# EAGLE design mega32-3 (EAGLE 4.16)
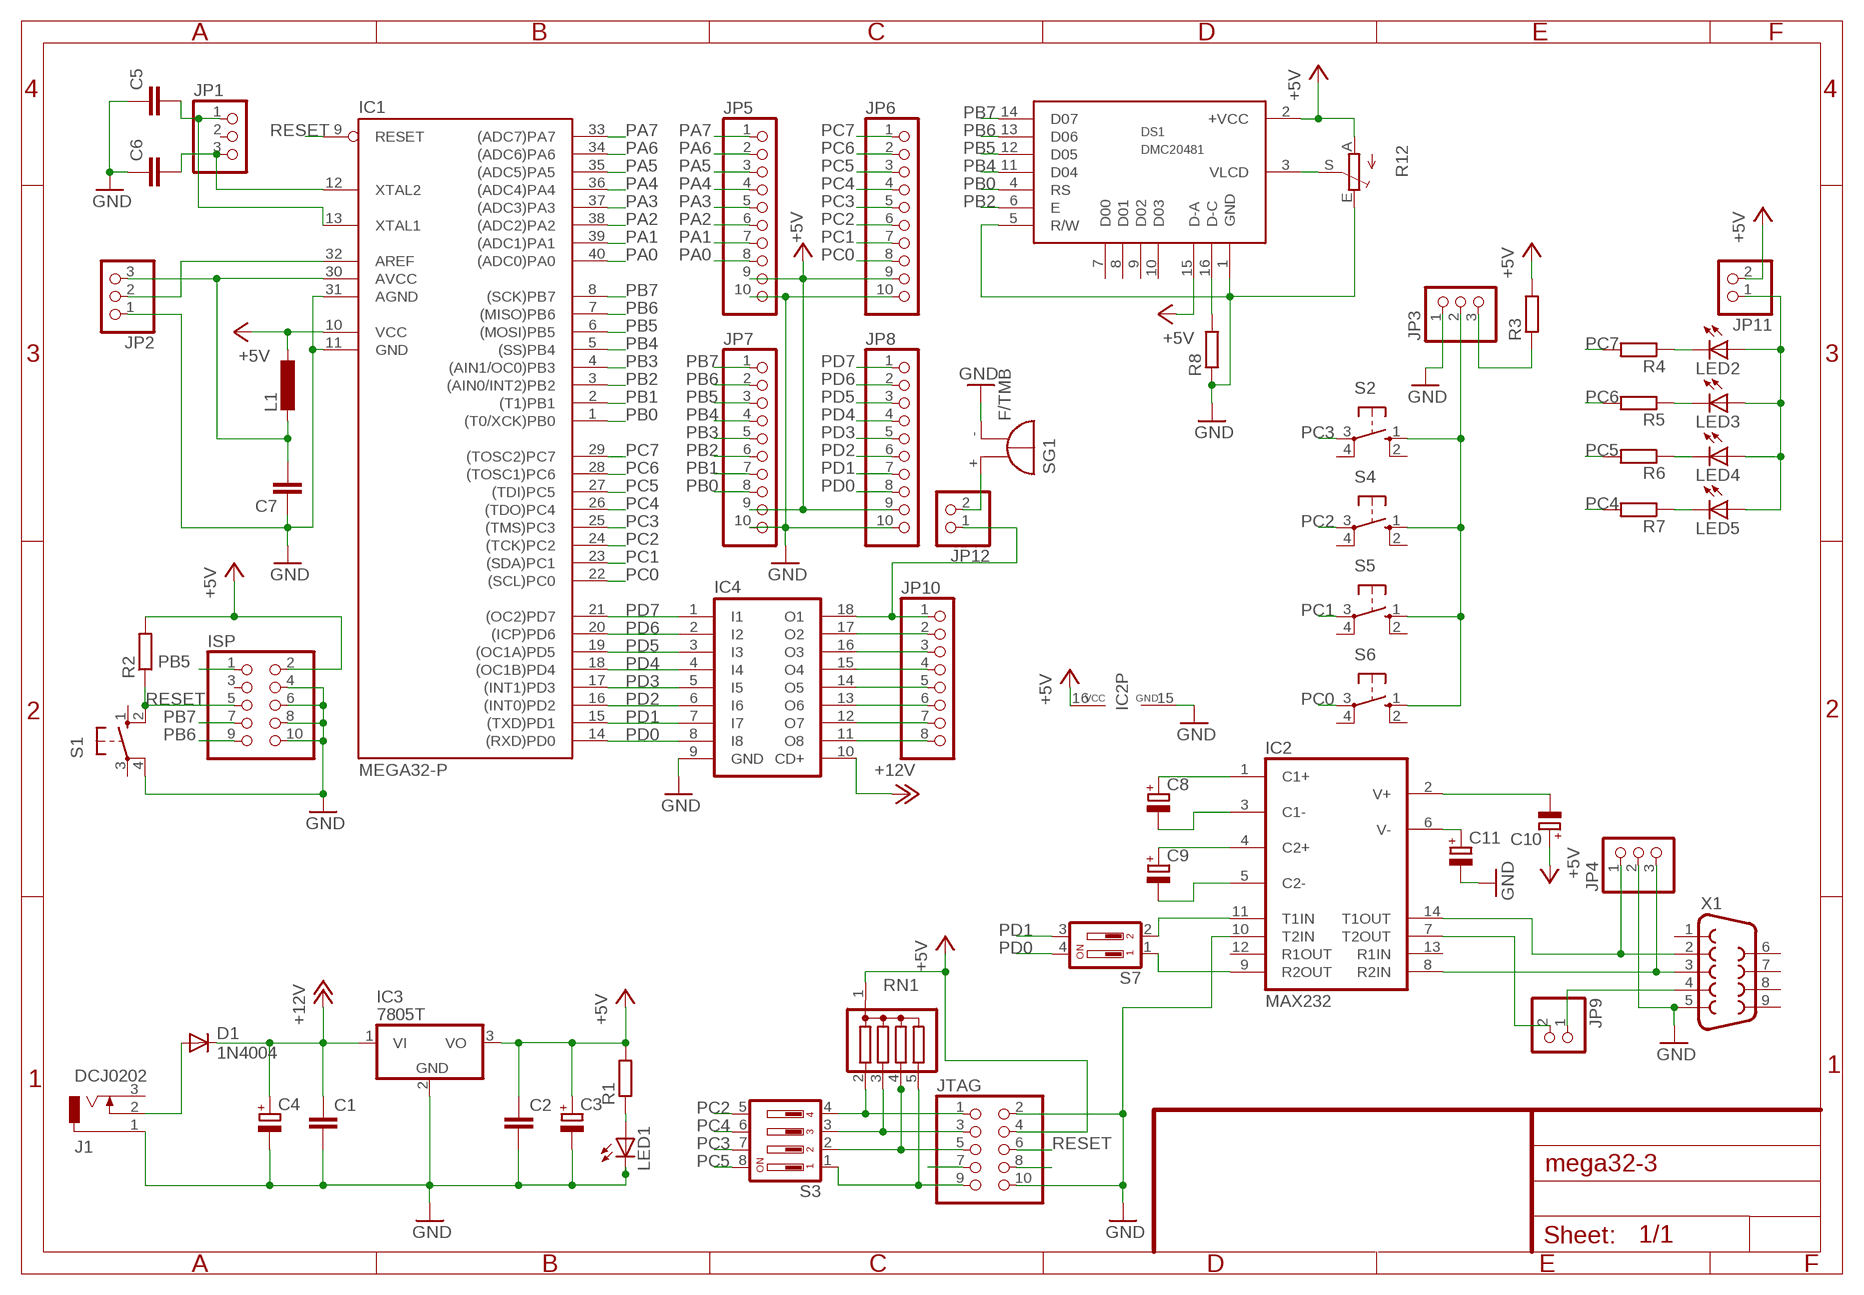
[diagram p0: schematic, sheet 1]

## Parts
C1  C-EU050-024X044  [C050-024X044]
C2  C-EU050-024X044  [C050-024X044]
C3  CPOL-EUE2.5-6  [E2,5-6]
C4  CPOL-EUE2.5-7  [E2,5-7]
C5  C-EU050-024X044  [C050-024X044]
C6  C-EU050-024X044  [C050-024X044]
C7  C-EU050-024X044  [C050-024X044]
C8  CPOL-EUE2.5-6  [E2,5-6]
C9  CPOL-EUE2.5-6  [E2,5-6]
C10  CPOL-EUE2.5-6  [E2,5-6]
C11  CPOL-EUE2.5-6  [E2,5-6]
D1  1N4004  [DO41-10]
DS1  DMC20481  [DM20481]
IC1  MEGA32-P  [DIL40]
IC2  MAX232  [DIL16]
IC3  7805T  [TO220H]
IC4  ULN2803A  [DIL18]
ISP  PINHD-2X5  [2X05]
J1  DCJ0202  [DCJ0202]
JP1  PINHD-1X3  [1X03]
JP2  PINHD-1X3  [1X03]
JP3  PINHD-1X3  [1X03]
JP4  PINHD-1X3  [1X03]
JP5  PINHD-1X10  [1X10]
JP6  PINHD-1X10  [1X10]
JP7  PINHD-1X10  [1X10]
JP8  PINHD-1X10  [1X10]
JP9  PINHD-1X2  [1X02]
JP10  PINHD-1X8  [1X08]
JP11  PINHD-1X2  [1X02]
JP12  PINHD-1X2  [1X02]
JTAG  PINHD-2X5  [2X05]
L1  L-EU0207/10  [0207/10]
LED1  LED5MM  [LED5MM]
LED2  LED5MM  [LED5MM]
LED3  LED5MM  [LED5MM]
LED4  LED5MM  [LED5MM]
LED5  LED5MM  [LED5MM]
R1  R-EU_0207/10  [0207/10]
R2  R-EU_0207/10  [0207/10]
R3  R-EU_0207/10  [0207/10]
R4  R-EU_0207/10  [0207/10]
R5  R-EU_0207/10  [0207/10]
R6  R-EU_0207/10  [0207/10]
R7  R-EU_0207/10  [0207/10]
R8  R-EU_0207/10  [0207/10]
R12  TRIM_EU-B64Y  [B64Y]
RN1  G04R  [SIL5]
S1  10-XX  [B3F-10XX]
S2  10-XX  [B3F-10XX]
S3  DIP04YL  [DIP04YL]
S4  10-XX  [B3F-10XX]
S5  10-XX  [B3F-10XX]
S6  10-XX  [B3F-10XX]
S7  DIP02YL  [DIP02YL]
SG1  F/TMB  [F/TMB]
X1  F09H  [F09H]

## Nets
+5V: C2.1 C3.+ C10.+ DS1.2(+VCC) DS1.15(D-A) IC1.10(VCC) IC2.16(VCC) IC3.3(VO) ISP.2 JP5.9 JP6.9 JP7.9 JP8.9 JP11.2 JTAG.4 L1.1 R1.2 R2.2 R3.2 R12.A RN1.1
+12V: C1.1 C4.+ D1.C IC3.1(VI) IC4.10(CD+)
GND: C1.2 C2.2 C3.- C4.- C5.1 C6.1 C7.1 C11.- DS1.1(GND) DS1.5(R/W) IC1.11(GND) IC1.31(AGND) IC2.10(T2IN) IC2.15(GND) IC3.2(GND) IC4.9(GND) ISP.4 ISP.6 ISP.8 ISP.10 J1.1 JP2.1 JP3.1 JP4.2 JP5.10 JP6.10 JP7.10 JP8.10 JTAG.2 JTAG.10 LED1.K(C) R8.1 R12.E S1.4(P1) SG1.- X1.5
N$1: C7.2 IC1.30(AVCC) JP2.3 L1.2
N$2: IC1.32(AREF) JP2.2
N$4: JP3.2 S2.1(S) S4.1(S) S5.1(S) S6.1(S)
N$5: C8.+ IC2.1(C1+)
N$6: C8.- IC2.3(C1-)
N$7: C9.+ IC2.4(C2+)
N$8: C9.- IC2.5(C2-)
N$9: IC2.14(T1OUT) JP4.1 X1.2
N$10: IC2.8(R2IN) JP4.3 X1.3
N$11: C10.- IC2.2(V+)
N$12: C11.+ IC2.6(V-)
N$13: IC2.11(T1IN) S7.2
N$14: IC2.9(R2OUT) S7.1
N$15: JP3.3 R3.1
N$16: JP9.1 X1.4
N$17: JTAG.7
N$18: IC4.18(O1) JP10.1 JP12.1
N$19: DS1.16(D-C) R8.2
N$20: JTAG.8
N$21: JP12.2 SG1.+
N$23: LED5.K(C) R7.1
N$24: LED4.K(C) R6.1
N$25: LED3.K(C) R5.1
N$26: LED2.K(C) R4.1
N$27: IC2.7(T2OUT) JP9.2
N$29: DS1.3(VLCD) R12.S
N$30: C5.2 IC1.13(XTAL1) JP1.1
N$31: C6.2 IC1.12(XTAL2) JP1.3
N$32: IC4.17(O2) JP10.2
N$33: IC4.16(O3) JP10.3
N$34: IC4.15(O4) JP10.4
N$35: IC4.14(O5) JP10.5
N$36: IC4.13(O6) JP10.6
N$37: IC4.12(O7) JP10.7
N$38: IC4.11(O8) JP10.8
N$39: JP11.1 LED2.A LED3.A LED4.A LED5.A
N$71: D1.A J1.2
N$73: LED1.A R1.1
N$111: JTAG.3 RN1.3 S3.3
N$222: JTAG.1 RN1.2 S3.4
N$333: JTAG.5 RN1.4 S3.2
N$444: JTAG.9 RN1.5 S3.1
PA0: IC1.40((ADC0)PA0) JP5.8
PA1: IC1.39((ADC1)PA1) JP5.7
PA2: IC1.38((ADC2)PA2) JP5.6
PA3: IC1.37((ADC3)PA3) JP5.5
PA4: IC1.36((ADC4)PA4) JP5.4
PA5: IC1.35((ADC5)PA5) JP5.3
PA6: IC1.34((ADC6)PA6) JP5.2
PA7: IC1.33((ADC7)PA7) JP5.1
PB0: DS1.4(RS) IC1.1((T0/XCK)PB0) JP7.8
PB1: IC1.2((T1)PB1) JP7.7
PB2: DS1.6(E) IC1.3((AIN0/INT2)PB2) JP7.6
PB3: IC1.4((AIN1/OC0)PB3) JP7.5
PB4: DS1.11(D04) IC1.5((SS)PB4) JP7.4
PB5: DS1.12(D05) IC1.6((MOSI)PB5) ISP.1 JP7.3
PB6: DS1.13(D06) IC1.7((MISO)PB6) ISP.9 JP7.2
PB7: DS1.14(D07) IC1.8((SCK)PB7) ISP.7 JP7.1
PC0: IC1.22((SCL)PC0) JP6.8 S6.3(P)
PC1: IC1.23((SDA)PC1) JP6.7 S5.3(P)
PC2: IC1.24((TCK)PC2) JP6.6 S3.5 S4.3(P)
PC3: IC1.25((TMS)PC3) JP6.5 S2.3(P) S3.7
PC4: IC1.26((TDO)PC4) JP6.4 R7.2 S3.6
PC5: IC1.27((TDI)PC5) JP6.3 R6.2 S3.8
PC6: IC1.28((TOSC1)PC6) JP6.2 R5.2
PC7: IC1.29((TOSC2)PC7) JP6.1 R4.2
PD0: IC1.14((RXD)PD0) IC4.8(I8) JP8.8 S7.4
PD1: IC1.15((TXD)PD1) IC4.7(I7) JP8.7 S7.3
PD2: IC1.16((INT0)PD2) IC4.6(I6) JP8.6
PD3: IC1.17((INT1)PD3) IC4.5(I5) JP8.5
PD4: IC1.18((OC1B)PD4) IC4.4(I4) JP8.4
PD5: IC1.19((OC1A)PD5) IC4.3(I3) JP8.3
PD6: IC1.20((ICP)PD6) IC4.2(I2) JP8.2
PD7: IC1.21((OC2)PD7) IC4.1(I1) JP8.1
RESET: IC1.9(RESET) ISP.5 JTAG.6 R2.1 S1.2(S1)
Unconnected: DS1.7(D00) DS1.8(D01) DS1.9(D02) DS1.10(D03) IC2.12(R1OUT) IC2.13(R1IN) ISP.3 J1.3 JP1.2 S1.1(S) S1.3(P) S2.2(S1) S2.4(P1) S4.2(S1) S4.4(P1) S5.2(S1) S5.4(P1) S6.2(S1) S6.4(P1) X1.1 X1.6 X1.7 X1.8 X1.9

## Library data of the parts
C1 C2 C5-C7 = rcl:C-EU: CAPACITOR, European symbol
C3 C4 C8-C11 = rcl:CPOL-EU: POLARIZED CAPACITOR, European symbol
D1 = diode:1N4004: DIODE
DS1 = abi-lcd:DMC20481
IC1 = atmel:MEGA32-P: MICROCONTROLLER 32 Kbytes FLASH 2 Kbytes SRAM 1 Kbytes EEPROM USART 8-channel 10 bit ADC Source: www.atmel.com .. doc2503.pdf
IC2 = maxim:MAX232: RS232 TRANSEIVER
IC3 = linear:78*: Positive VOLTAGE REGULATOR Source: http://cache.national.com/ds/LM/LM78L05.pdf http://www.fairchildsemi.com/ds/LM/LM7805.pdf
IC4 = uln-udn:ULN2803A: DRIVER ARRAY
ISP JTAG = pinhead:PINHD-2X5: PIN HEADER
J1 = con-jack:DCJ0202: DC POWER JACK Source: DCJ0202.pdf
JP1-JP4 = pinhead:PINHD-1X3: PIN HEADER
JP5-JP8 = pinhead:PINHD-1X10: PIN HEADER
JP9 JP11 JP12 = pinhead:PINHD-1X2: PIN HEADER
JP10 = pinhead:PINHD-1X8: PIN HEADER
L1 = rcl:L-EU: INDUCTOR, European symbol
LED1-LED5 = led:LED: LED
R1-R8 = rcl:R-EU_: RESISTOR, European symbol
R12 = pot:TRIM_EU-: POTENTIOMETER
RN1 = resistor-sil:G04R: SIL RESISTOR
S1 S2 S4-S6 = switch-omron:10-XX: OMRON SWITCH
S3 = switch-dil:DIP04YL: DIL/CODE SWITCH
S7 = switch-dil:DIP02YL: DIL/CODE SWITCH
SG1 = buzzer:F/TMB: BUZZER
X1 = con-subd:F09: SUB-D

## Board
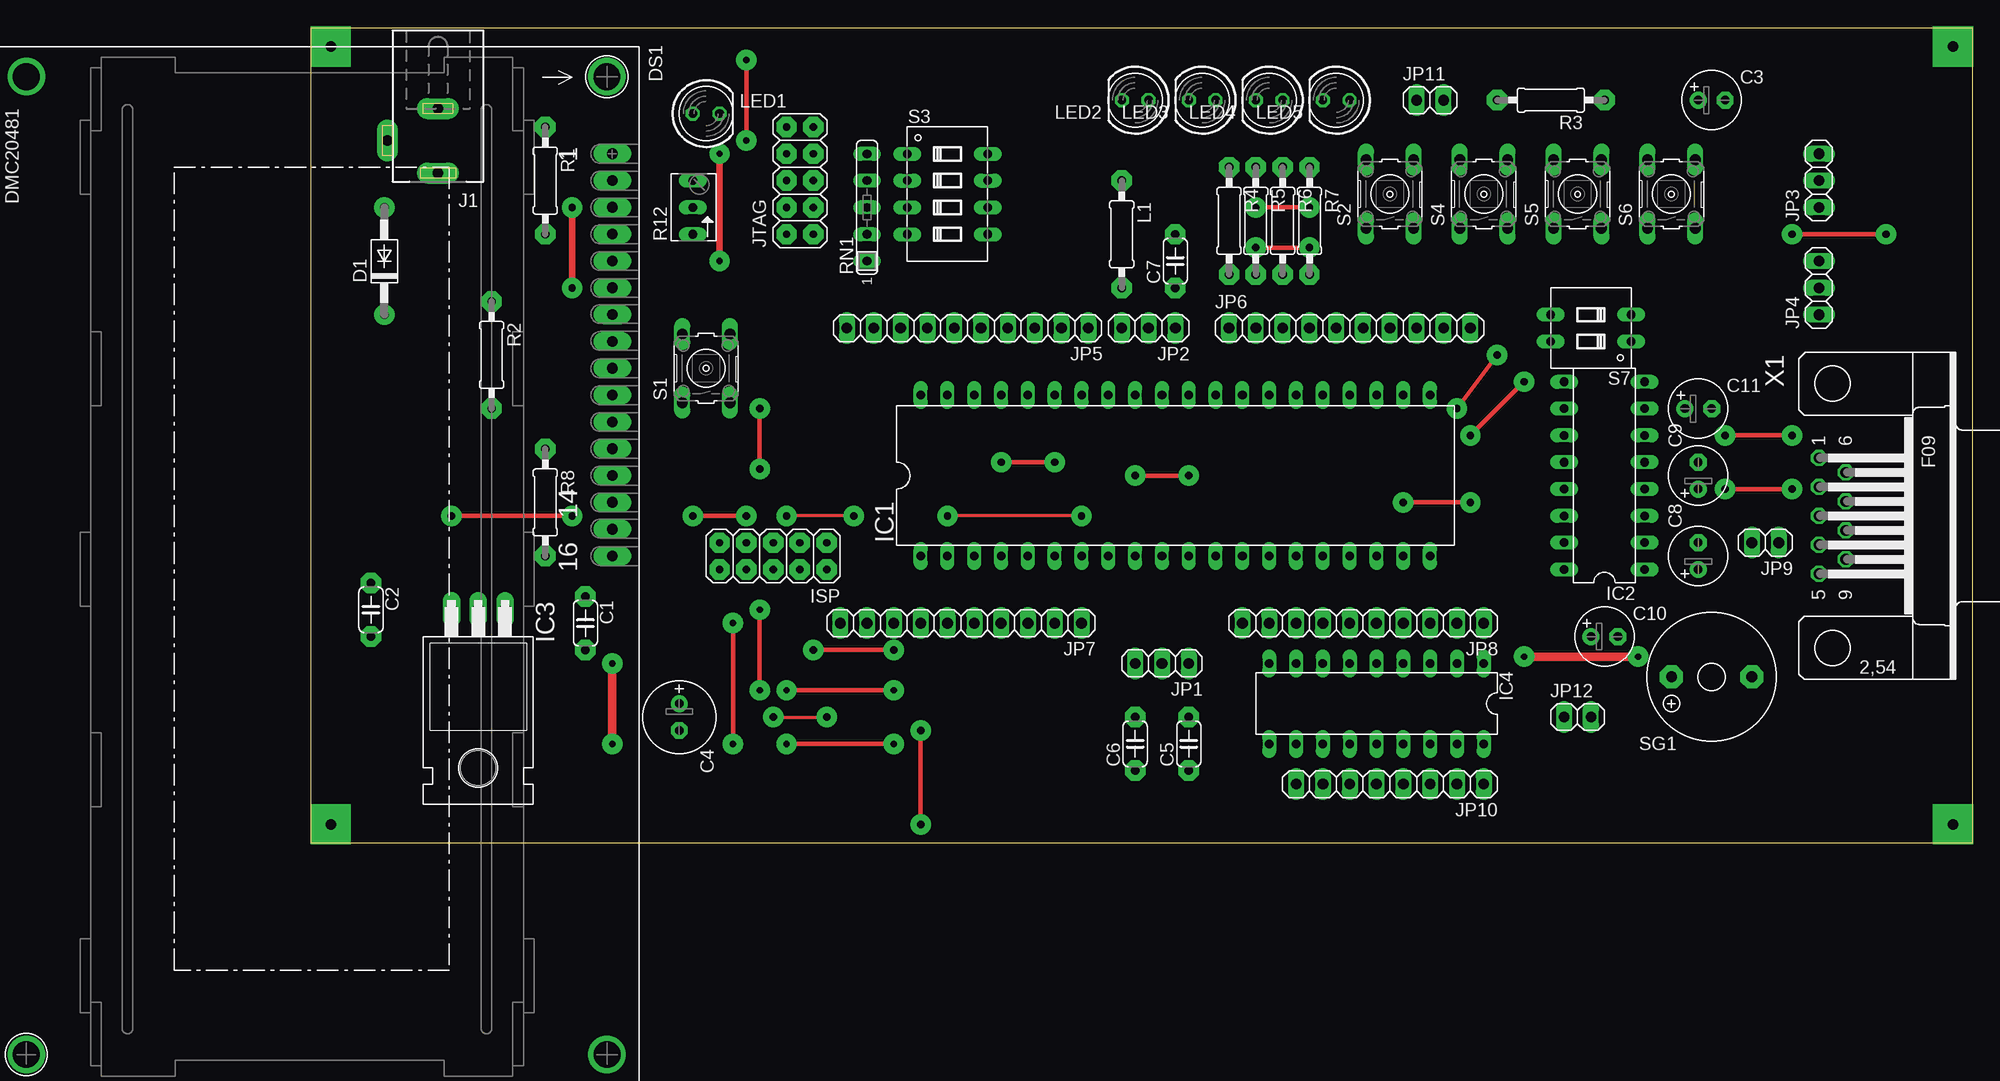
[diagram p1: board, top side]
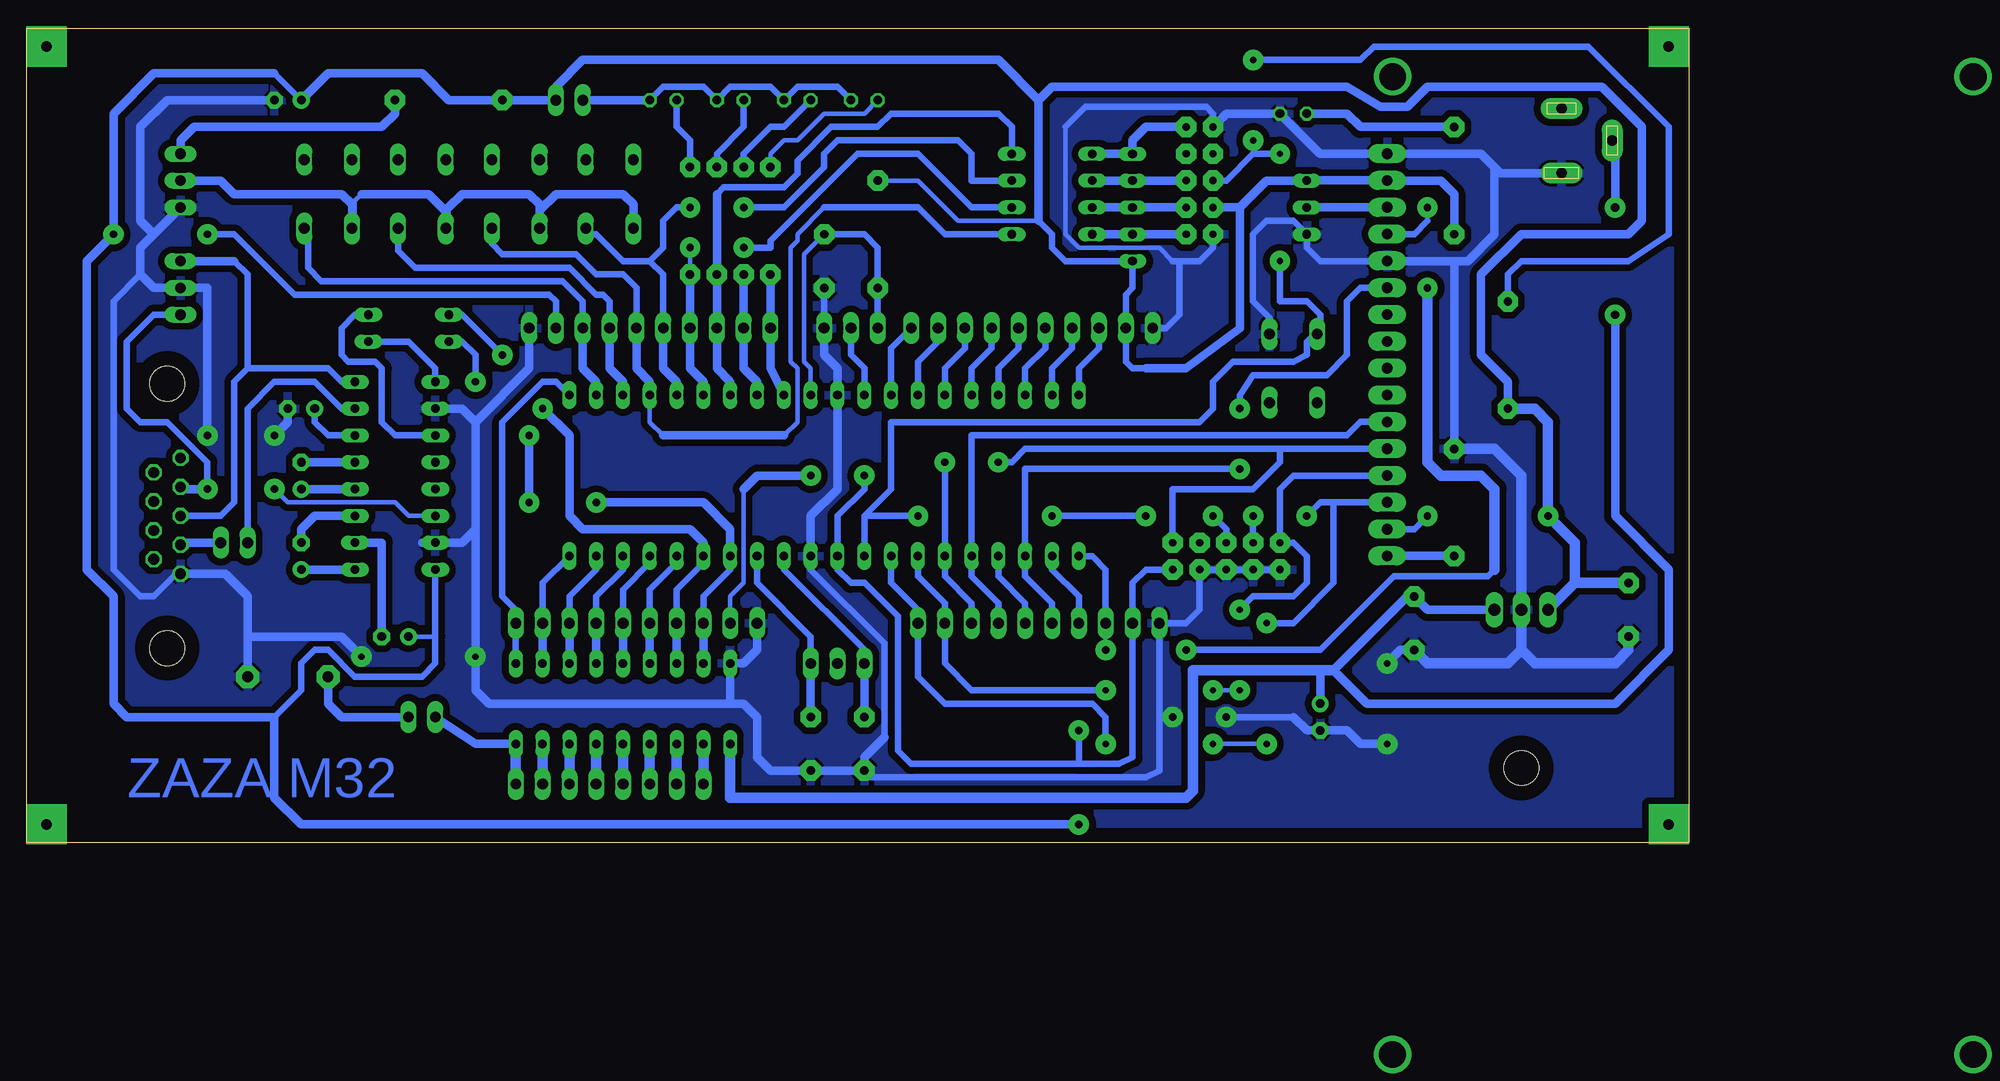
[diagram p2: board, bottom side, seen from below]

Size 157.46 x 77.14 mm. Coordinates in mm from the lower left corner, seen from the top.
Outline: 0,0 157.46,0 157.46,77.14 0,77.14 0,0
Copper layers (1*16): Top 0.035mm / dielectric 1.5mm / Bottom 0.035mm
Design rules "default": minimum track width 10mil, minimum drill 24mil, track to track 25mil, track to pad 25mil, pad to pad 25mil, via to via 25mil, smd to smd 25mil, copper to edge 55mil, drill to drill 10mil, minimum pad ring 10mil, minimum via ring 8mil, stop-mask expansion 4mil, vias tented up to drill 0mil, thermal gap 10mil

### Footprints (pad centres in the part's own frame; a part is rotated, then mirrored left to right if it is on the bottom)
C050-024X044 = drill 0.8 pad 1.93 octagon: 1 -2.54,0; 2 2.54,0
E2,5-6 = drill 0.813 pad 1.6 round: + -1.27,0 | drill 0.813 pad 1.6 octagon: - 1.27,0
E2,5-7 = drill 0.813 pad 1.6 round: + -1.27,0 | drill 0.813 pad 1.6 octagon: - 1.27,0
DO41-10 = drill 0.8 pad 1.93 round: A 5.08,0; C -5.08,0
DM20481 = drill 1.016 pad 1.778 long: 1 -39.383,29.21; 2 -36.843,29.21; 3 -34.303,29.21; 4 -31.763,29.21; 5 -29.223,29.21; 6 -26.683,29.21; 7 -24.143,29.21; 8 -21.603,29.21; 9 -19.063,29.21; 10 -16.523,29.21; 11 -13.983,29.21; 12 -11.443,29.21; 13 -8.903,29.21; 14 -6.363,29.21; 15 -3.823,29.21; 16 -1.283,29.21 | drill 2.54 pad 0.254 round: P$1 -46.672,-26.289; P$2 45.936,-26.289; P$3 45.936,28.715; P$4 -46.672,28.702
DIL40 = drill 0.813 long: 1 -24.13,-7.62; 2 -21.59,-7.62; 3 -19.05,-7.62; 4 -16.51,-7.62; 5 -13.97,-7.62; 6 -11.43,-7.62; 7 -8.89,-7.62; 8 -6.35,-7.62; 9 -3.81,-7.62; 10 -1.27,-7.62; 11 1.27,-7.62; 12 3.81,-7.62; 13 6.35,-7.62; 14 8.89,-7.62; 15 11.43,-7.62; 16 13.97,-7.62; 17 16.51,-7.62; 18 19.05,-7.62; 19 21.59,-7.62; 20 24.13,-7.62; 21 24.13,7.62; 22 21.59,7.62; 23 19.05,7.62; 24 16.51,7.62; 25 13.97,7.62; 26 11.43,7.62; 27 8.89,7.62; 28 6.35,7.62; 29 3.81,7.62; 30 1.27,7.62; 31 -1.27,7.62; 32 -3.81,7.62; 33 -6.35,7.62; 34 -8.89,7.62; 35 -11.43,7.62; 36 -13.97,7.62; 37 -16.51,7.62; 38 -19.05,7.62; 39 -21.59,7.62; 40 -24.13,7.62
DIL16 = drill 0.813 long: 1 -8.89,-3.81; 2 -6.35,-3.81; 3 -3.81,-3.81; 4 -1.27,-3.81; 5 1.27,-3.81; 6 3.81,-3.81; 7 6.35,-3.81; 8 8.89,-3.81; 9 8.89,3.81; 10 6.35,3.81; 11 3.81,3.81; 12 1.27,3.81; 13 -1.27,3.81; 14 -3.81,3.81; 15 -6.35,3.81; 16 -8.89,3.81
TO220H = drill 1.118 long: 1 -2.54,-10.16; 2 0,-10.16; 3 2.54,-10.16 | hole 3.302: 0,4.826
DIL18 = drill 0.813 long: 1 -10.16,-3.81; 2 -7.62,-3.81; 3 -5.08,-3.81; 4 -2.54,-3.81; 5 0,-3.81; 6 2.54,-3.81; 7 5.08,-3.81; 8 7.62,-3.81; 9 10.16,-3.81; 10 10.16,3.81; 11 7.62,3.81; 12 5.08,3.81; 13 2.54,3.81; 14 0,3.81; 15 -2.54,3.81; 16 -5.08,3.81; 17 -7.62,3.81; 18 -10.16,3.81
2X05 = drill 0.7 pad 1.93 octagon: 1 -5.08,-1.27; 2 -5.08,1.27; 3 -2.54,-1.27; 4 -2.54,1.27; 5 0,-1.27; 6 0,1.27; 7 2.54,-1.27; 8 2.54,1.27; 9 5.08,-1.27; 10 5.08,1.27
DCJ0202 = drill 1 pad 2 long: 1 0,3.1; 2 4.8,0; 3 0,-3
1X03 = drill 1.016 long: 1 -2.54,0; 2 0,0; 3 2.54,0
1X10 = drill 1.016 long: 1 -11.43,0; 2 -8.89,0; 3 -6.35,0; 4 -3.81,0; 5 -1.27,0; 6 1.27,0; 7 3.81,0; 8 6.35,0; 9 8.89,0; 10 11.43,0
1X02 = drill 1.016 long: 1 -1.27,0; 2 1.27,0
1X08 = drill 1.016 long: 1 -8.89,0; 2 -6.35,0; 3 -3.81,0; 4 -1.27,0; 5 1.27,0; 6 3.81,0; 7 6.35,0; 8 8.89,0
0207/10 = drill 0.8 pad 1.93 octagon: 1 -5.08,0; 2 5.08,0
LED5MM = drill 0.813 octagon: A -1.27,0; K 1.27,0
B64Y = drill 0.813 long: A 2.54,0; E -2.54,0; S 0,0
SIL5 = drill 0.813 long: 1 -5.08,0; 2 -2.54,0; 3 0,0; 4 2.54,0; 5 5.08,0
B3F-10XX = drill 1.016 long: 1 -3.251,2.261; 2 3.251,2.261; 3 -3.251,-2.261; 4 3.251,-2.261
DIP04YL = drill 0.813 long: 1 -3.81,-3.81; 2 -1.27,-3.81; 3 1.27,-3.81; 4 3.81,-3.81; 5 3.81,3.81; 6 1.27,3.81; 7 -1.27,3.81; 8 -3.81,3.81
DIP02YL = drill 0.813 long: 1 -1.27,-3.81; 2 1.27,-3.81; 3 1.27,3.81; 4 -1.27,3.81
F/TMB = drill 1.016 pad 2.159 octagon: + 3.81,0; - -3.81,0
F09H = drill 1.016 octagon: 1 -5.486,-1.27; 2 -2.743,-1.27; 3 0,-1.27; 4 2.743,-1.27; 5 5.486,-1.27; 6 -4.115,1.27; 7 -1.372,1.27; 8 1.372,1.27; 9 4.115,1.27 | hole 3.302: -12.522,0; 12.522,0

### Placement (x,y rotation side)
C1  26.03,20.79 270 top
C2  5.71,22.06 270 top
C3  132.71,70.32 0 top
C4  34.92,11.9 270 top
C5  83.18,9.36 90 top
C6  78.1,9.36 90 top
C7  81.91,55.08 90 top
C8  131.44,27.14 90 top
C9  131.44,34.76 90 top
C10  122.55,19.52 0 top
C11  131.44,41.11 0 top
D1  6.98,55.08 90 top
DS1  -0.64,25.87 270 top
IC1  81.91,34.76 0 top
IC2  122.55,34.76 90 top
IC3  15.87,11.9 180 top
IC4  100.96,13.17 180 top
ISP  43.81,27.14 180 top
J1  12.06,66.51 180 top
JP1  80.64,16.98 180 top
JP2  79.37,48.73 180 top
JP3  142.87,62.7 90 top
JP4  142.87,52.54 90 top
JP5  62.23,48.73 180 top
JP6  98.42,48.73 0 top
JP7  61.59,20.79 180 top
JP8  99.69,20.79 180 top
JP9  137.79,28.41 180 top
JP10  102.23,5.55 180 top
JP11  106.04,70.32 0 top
JP12  120.01,11.9 0 top
JTAG  46.35,62.7 90 top
L1  76.83,57.62 270 top
LED1  37.46,69.05 0 top
LED2  78.1,70.32 180 top
LED3  84.45,70.32 180 top
LED4  90.8,70.32 180 top
LED5  97.15,70.32 180 top
R1  22.22,62.7 270 top
R2  17.14,46.19 270 top
R3  117.47,70.32 180 top
R4  86.99,58.89 270 top
R5  89.53,58.89 270 top
R6  92.07,58.89 270 top
R7  94.61,58.89 270 top
R8  22.22,32.22 270 top
R12  36.19,60.16 90 top
RN1  52.7,60.16 90 top
S1  37.46,44.92 90 top
S2  102.23,61.43 90 top
S3  60.32,61.43 270 top
S4  111.12,61.43 90 top
S5  120.01,61.43 90 top
S6  128.9,61.43 90 top
S7  121.28,48.73 90 top
SG1  132.71,15.71 180 top
X1  144.14,30.95 270 top

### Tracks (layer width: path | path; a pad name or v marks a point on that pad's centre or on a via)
+5V  (via drill 0.7 pad 1.93)
  Top 0.406: v149.22,57.62 v140.33,57.62 | v78.1,34.76 v83.18,34.76 | v57.78,1.74 v57.78,10.63 | v13.33,30.95 v24.76,30.95
  Bottom 0.406: DS1.2 | R12.A 36.18,62.71 | 61.59,58.89 69.21,58.89 73.02,62.7 L1.1 | JP8.9 90.8,23.33 89.53,24.6 89.53,33.49 | 118.74,19.52 C10.+
  Bottom 0.61: 61.59,58.89 60.32,57.62 60.32,56.35 59.05,55.08 RN1.1 52.7,52.54 53.34,51.91 JP5.9 53.34,45.56 52.7,44.92 51.43,44.92 | JP6.9 107.31,51.27 107.94,51.91 132.07,51.91 137.79,57.62 v140.33,57.62 | C3.+ 133.98,72.86 | IC2.16 118.74,19.52 118.74,16.98 120.01,15.71 126.36,15.71 128.9,18.25 130.17,18.25 131.44,16.98 131.44,14.44 133.98,11.9 | v78.1,34.76 78.1,33.49 80.64,30.95 IC1.10 80.64,25.87 79.37,24.6 78.1,24.6 74.92,21.43 74.92,8.73 73.66,7.46 57.78,7.46 | 57.78,7.46 53.97,7.46 52.7,8.09 JP7.9 52.7,24.6 51.43,25.87 ISP.2 | DS1.15 26.02,29.69 v24.76,30.95 | v57.78,10.63 57.78,7.46
  Bottom 0.813: R1.2 22.22,61.43 23.49,62.7 DS1.2 | 36.18,62.71 DS1.2 | R12.A 40,62.7 42.54,60.16 | 42.54,60.16 JTAG.4 | 51.43,44.92 47.62,44.92 42.54,48.73 42.54,60.16 | C3.+ 128.9,72.86 120.01,72.86 117.47,70.32 R3.2 JP11.2 107.31,71.59 104.77,74.13 65.4,74.13 61.59,70.32 | 133.98,72.86 145.41,72.86 149.22,69.05 v149.22,57.62 151.76,55.08 151.76,25.87 149.22,23.33 149.22,13.17 147.95,11.9 133.98,11.9 133.98,4.28 131.44,1.74 v57.78,1.74 | 89.53,33.49 88.26,34.76 v83.18,34.76 | 61.59,70.32 61.59,58.89 | R2.2 17.14,43.65 19.68,46.19 19.68,53.81 15.87,57.62 5.71,57.62 4.44,58.89 4.44,67.78 8.25,71.59 24.76,71.59 26.66,69.69 29.2,69.69 32.38,71.59 60.32,71.59 61.59,70.32
  Bottom 1.016: 10.79,24.6 IC3.3 | C2.1 10.79,24.6 | 10.79,24.6 10.79,28.41 v13.33,30.95 13.33,39.84 14.6,41.11 R2.2
+12V
  Bottom 0.813: D1.C 6.98,30.95 1.9,25.87 1.9,18.25 6.98,13.17 30.47,13.17 33.65,16.34 26.66,23.33 C1.1 24.76,22.06 IC3.1 | 34.92,16.34 C4.+
  Bottom 1.016: IC4.10 90.8,4.28 47.62,4.28 46.98,4.91 46.98,16.34 34.92,16.34 33.65,16.34
GND  (via drill 0.6 pad 1.93, 0.7 pad 1.93)
  Top 0.305: v43.81,11.9 v48.89,11.9
  Top 0.406: v140.33,38.57 v133.98,38.57
  Top 0.813: v28.57,16.98 v28.57,9.36 | v114.93,17.61 v125.72,17.61
  Bottom 0.305: v48.89,11.9 50.16,11.9
  Bottom 0.406: 34.93,65.25 DS1.1 | 48.89,55.08 50.16,56.35 57.78,56.35 59.05,57.62 59.05,67.78 | DS1.5 | 138.65,25.46 X1.5
  Bottom 0.61: JP2.1 C7.1 | JTAG.2 45.08,56.35 46.35,55.08 48.26,55.08 | 48.89,55.08 48.26,55.08 | DS1.5 34.92,55.08 36.19,56.35 R12.E 37.46,58.89 40,58.89 41.27,57.62 41.27,51.27 39.72,49.72 S1.4 | JTAG.10 45.08,69.05 45.72,69.69 57.15,69.69 59.05,67.78 | 37.46,11.9 v43.81,11.9 | ISP.10 ISP.8 ISP.6 ISP.4 46.35,22.06 47.62,20.79 JP7.10 50.16,11.9 50.16,6.82 51.43,6.18 77.46,6.18 C6.1 | IC1.11 83.18,25.87 76.19,18.89 76.19,10 | 143.28,25.46 145.41,23.33 146.68,23.33 149.22,25.87 149.22,51.27 146.68,53.81 | JP5.10 49.53,48.73 48.26,50 48.26,55.08
  Bottom 0.813: JP2.1 81.91,46.19 80.64,44.92 IC1.31 80.64,33.49 83.18,30.95 IC1.11 | 145.41,57.62 146.68,56.35 146.68,53.81 145.41,52.54 JP4.2 140.33,52.54 v140.33,38.57 | 114.93,29.68 116.2,28.41 IC2.15 120.01,28.41 | 114.93,29.68 114.93,39.84 | 114.93,39.84 116.2,41.11 IC2.10 | JP8.10 88.26,18.25 89.53,16.98 IC4.9 90.8,13.17 | 90.8,13.17 113.66,13.17 114.93,14.44 v114.93,17.61 114.93,29.68 | JP6.10 109.85,44.92 114.93,39.84 | JTAG.10 43.81,69.05 LED1.K 34.93,65.25 19.69,65.25 18.41,63.97 | 18.41,63.97 18.41,57.62 20.95,55.08 22.22,55.08 | 22.22,55.08 DS1.5 | J1.1 17.85,63.41 18.41,63.97 | R8.1 22.22,55.08 | 90.8,13.17 89.53,13.17 88.26,11.9 88.26,8.09 86.99,6.82 C5.1 C6.1 78.1,8.09 76.19,10 | 145.41,57.62 JP3.1 | C3.- 144.14,70.32 146.68,67.78 146.68,58.89 145.41,57.62 | 136.52,19.52 SG1.- | 136.52,19.52 136.52,23.33 138.65,25.46 143.28,25.46 | 136.52,19.52 127.63,19.52 v125.72,17.61 | 37.46,11.9 36.19,10.63 C4.- 32.38,10.63 31.11,9.36 v28.57,9.36 | C1.2 27.3,18.25 v28.57,16.98 | C11.- 132.71,39.84 v133.98,38.57
  Bottom 1.016: C2.2 5.71,18.25 6.98,16.98 14.6,16.98 15.87,18.25 | 15.87,18.25 IC3.2 15.87,34.76 18.41,37.3 R8.1 | 15.87,18.25 17.14,16.98 24.76,16.98 C1.2
  pour Bottom: -0.64,79.21 -0.64,-2.07 0.63,-3.34 156.84,-3.34 160.65,0.47 160.65,76.67 156.84,80.48 0.63,80.48
N$1
  Bottom 0.406: IC1.30 83.18,44.92 83.81,45.56 83.81,55.72 C7.2
  Bottom 0.61: JP2.3 L1.2 76.83,56.35 78.1,57.62 C7.2
N$2
  Bottom 0.61: IC1.32 78.1,44.92 79.37,46.19 JP2.2
N$3  (via drill 1 pad 3.81)
  other vias: 1.9,1.74
N$4
  Bottom 0.406: 108.86,59.88 S4.1 | S5.1 117.55,58.18 117.47,58.26 117.47,60.16 | 125.72,61.43 126.36,60.8 126.36,58.26 126.44,58.18 S6.1
  Bottom 0.813: S2.1 99.97,60.44 100.96,61.43 107.31,61.43 108.86,59.88 | S4.1 108.86,60.44 109.85,61.43 116.2,61.43 117.47,60.16 | S5.1 117.75,59.8 119.38,61.43 125.72,61.43 | S6.1 126.64,60.44 127.63,61.43 137.79,61.43 139.06,62.7 JP3.2
N$5
  Bottom 0.813: IC2.1 C8.+
N$6
  Bottom 0.813: C8.- 131.44,29.68 130.17,30.95 IC2.3
N$7
  Bottom 0.813: IC2.4 C9.+
N$8
  Bottom 0.813: IC2.5 C9.-
N$9  (via drill 0.7 pad 1.93)
  Top 0.406: v133.98,33.49 v140.33,33.49
  Bottom 0.406: IC2.14 121.28,30.95 122.55,32.22 132.71,32.22 v133.98,33.49 | 142.87,33.49 X1.2
  Bottom 0.61: JP4.1 145.41,50 147.95,47.46 147.95,41.11 146.68,39.84 144.14,39.84 140.33,36.03 v140.33,33.49
  Bottom 0.813: v140.33,33.49 142.87,33.49
N$10
  Bottom 0.61: X1.3 139.06,30.95 137.79,32.22 137.79,43.65 136.52,44.92 | IC2.8 127.63,43.65 128.9,44.92 136.52,44.92 | 136.52,44.92 136.52,53.81 137.79,55.08
  Bottom 0.813: 137.79,55.08 JP4.3
N$11
  Bottom 0.813: C10.- 123.82,28.41 IC2.2
N$12
  Bottom 0.61: IC2.6 128.9,38.57 130.17,39.84 C11.+
N$13
  Bottom 0.61: IC2.11 122.55,38.57 123.82,39.84 123.82,44.92 124.45,45.56 126.99,45.56 127.63,46.19 127.63,48.73 126.36,50 S7.2
N$14
  Bottom 0.61: IC2.9 118.74,44.92 121.28,47.46 S7.1
N$15
  Bottom 0.813: R3.1 122.55,69.05 123.82,67.78 141.6,67.78 142.87,66.51 JP3.3
N$16
  Bottom 0.406: 142.87,28.41 X1.4
  Bottom 0.813: JP9.1 142.87,28.41
N$18
  Bottom 0.813: IC4.18 114.93,9.36 JP12.1
  Bottom 1.016: JP10.1 IC4.18
N$19
  Bottom 0.813: DS1.16 22.23,27.15 R8.2
N$21
  Bottom 0.813: JP12.2 127.63,11.9 128.9,13.17 SG1.+
N$23
  Bottom 0.61: R7.1 94.61,66.51 95.88,67.78 LED5.K
N$24
  Bottom 0.61: R6.1 92.07,65.24 89.53,67.78 LED4.K
N$25
  Bottom 0.61: R5.1 89.53,65.24 86.99,67.78 85.72,67.78 LED3.K
N$26
  Bottom 0.406: R4.1 86.99,65.24 85.72,66.51 84.45,66.51 81.91,69.05 78.1,69.05 LED2.K
N$27
  Bottom 0.61: JP9.2 136.52,41.11 133.98,43.65 130.17,43.65 127.63,41.11 IC2.7
N$28  (via drill 1 pad 3.81)
  other vias: 1.9,75.4
N$29
  Bottom 0.406: DS1.3
  Bottom 0.813: DS1.3 R12.S
N$30
  Bottom 0.61: IC1.13 88.26,24.6 83.18,19.52 JP1.1
  Bottom 0.813: C5.2 JP1.1
N$31
  Bottom 0.61: JP1.3 78.1,18.25 85.72,25.87 IC1.12
  Bottom 0.813: C6.2 JP1.3
N$32
  Bottom 1.016: JP10.2 IC4.17
N$33
  Bottom 1.016: JP10.3 IC4.16
N$34
  Bottom 1.016: JP10.4 IC4.15
N$35
  Bottom 1.016: JP10.5 IC4.14
N$36
  Bottom 1.016: JP10.6 IC4.13
N$37
  Bottom 1.016: JP10.7 IC4.12
N$38
  Bottom 1.016: JP10.8 IC4.11
N$39
  Bottom 0.61: LED2.A 80.64,71.59 84.45,71.59 LED3.A 86.99,71.59 90.8,71.59 LED4.A 93.34,71.59 97.15,71.59 LED5.A
  Bottom 0.813: LED5.A JP11.1
N$40  (via drill 1 pad 3.81)
  other vias: 155.57,75.4
N$41  (via drill 1 pad 3.81)
  other vias: 155.57,1.74
N$71
  Bottom 0.813: J1.2 6.98,66.51 D1.A
N$73
  Bottom 0.813: R1.1 31.11,67.78 32.38,69.05 LED1.A
N$111
  Bottom 0.813: S3.3 RN1.3 JTAG.3
N$222
  Bottom 0.813: S3.4 RN1.2 JTAG.1
N$333
  Bottom 0.813: S3.2 RN1.4 JTAG.5
N$444
  Bottom 0.813: S3.1 RN1.5 52.7,66.51 51.43,67.78 JTAG.9
PA0
  Bottom 0.61: JP5.8 55.88,46.83 57.78,44.92 IC1.40
PA1
  Bottom 0.61: JP5.7 58.41,46.83 60.32,44.92 IC1.39
PA2
  Bottom 0.61: JP5.6 60.96,46.83 62.86,44.92 IC1.38
PA3
  Bottom 0.61: JP5.5 63.5,46.83 65.4,44.92 IC1.37
PA4
  Bottom 0.61: JP5.4 66.03,46.83 67.94,44.92 IC1.36
PA5
  Bottom 0.61: JP5.3 68.57,46.83 70.48,44.92 IC1.35
PA6
  Bottom 0.61: JP5.2 71.11,47.46 73.02,45.56 IC1.34
PA7
  Bottom 0.61: JP5.1 75.56,46.83 IC1.33
PB0  (via drill 0.7 pad 1.93)
  Top 0.406: v47.62,18.25 v55.24,18.25
  Top 0.61: v24.76,52.54 v24.76,60.16
  Bottom 0.406: v24.76,60.16 24.76,58.89 | v55.24,18.25 JP7.8
  Bottom 0.61: DS1.4 26.02,57.63 24.76,58.89 | 18.41,25.87 19.04,25.24 27.93,25.24 34.92,18.25 v47.62,18.25 | JP7.8 55.24,25.87 56.51,27.14 IC1.1
  Bottom 1.016: v24.76,52.54 24.76,36.03 23.49,34.76 19.68,34.76 18.41,33.49 18.41,25.87
PB1
  Bottom 0.61: JP7.7 57.78,23.33 60.32,25.87 IC1.2
PB2  (via drill 0.7 pad 1.93)
  Top 0.406: v42.54,35.39 v42.54,41.11
  Bottom 0.61: DS1.6 31.1,52.55 32.38,51.27 32.38,46.19 34.29,44.28 41.27,44.28 42.54,42.38 v42.54,41.11 | v42.54,35.39 62.86,35.39 IC1.3 62.86,25.24 60.32,22.7 JP7.6
PB3
  Bottom 0.61: JP7.5 62.86,22.7 65.4,25.24 IC1.4
PB4
  Bottom 0.61: DS1.11 31.1,39.85 32.38,38.57 67.94,38.57 IC1.5 67.94,25.24 65.4,22.7 JP7.4
PB5  (via drill 0.7 pad 1.93)
  Top 0.406: v65.4,36.03 v70.48,36.03
  Bottom 0.61: DS1.12 31.1,37.31 32.38,37.3 38.73,37.3 | v70.48,36.03 IC1.6 70.48,25.24 67.94,22.7 JP7.3 | ISP.1 48.89,33.49 41.27,33.49 38.73,36.03 38.73,37.3 | v65.4,36.03 64.13,36.03 62.86,37.3 38.73,37.3
PB6  (via drill 0.6 pad 1.93)
  Top 0.406: v42.54,14.44 v42.54,22.06 | v45.08,14.44 v55.24,14.44
  Bottom 0.406: v42.54,14.44 v45.08,14.44
  Bottom 0.61: DS1.13 37.45,34.77 38.73,33.49 ISP.9 37.46,28.41 36.19,27.14 36.19,24.6 37.46,23.33 41.27,23.33 v42.54,22.06 | v55.24,14.44 67.94,14.44 70.48,16.98 JP7.2 70.48,22.7 73.02,25.24 IC1.7
PB7  (via drill 0.6 pad 1.93, 0.7 pad 1.93)
  Top 0.406: v36.19,30.95 v41.27,30.95 | v45.08,9.36 v55.24,9.36 | v40,9.36 v40,20.79
  Bottom 0.406: DS1.14 | v40,9.36 v45.08,9.36
  Bottom 0.61: v41.27,30.95 ISP.7 | v36.19,30.95 34.92,32.22 33.65,32.22 | 33.65,32.22 DS1.14 | v55.24,9.36 55.24,11.9 56.51,13.17 70.48,13.17 73.02,15.71 JP7.1 73.02,22.06 75.56,24.6 IC1.8 | v40,20.79 37.46,20.79 33.65,24.6 33.65,32.22
PC0
  Bottom 0.406: 131.36,58.18 131.44,58.26 | 131.36,58.18 S6.3 | 130.81,57.62 131.36,58.18
  Bottom 0.61: JP6.8 104.77,51.27 106.67,53.17 129.53,53.17 130.81,54.45 130.81,57.62
  Bottom 0.813: IC1.22 103.5,43.65 104.77,44.92 JP6.8
PC1
  Bottom 0.61: S5.3 122.27,56.07 120.64,54.45 106.04,54.45 103.5,51.91 102.86,51.91 102.23,51.27 JP6.7
  Bottom 0.813: IC1.23 100.96,43.65 102.23,44.92 JP6.7
PC2
  Bottom 0.406: 98.42,43.65 IC1.24 98.42,39.84 97.15,38.57 | 85.72,38.57 84.45,39.84 84.45,44.92 85.08,45.56 85.08,56.35 84.45,56.98 84.45,57.62 81.91,60.16
  Bottom 0.61: S4.3 113.38,56.71 112.39,55.72 105.41,55.72 103.5,53.81 100.96,53.81 99.69,52.54 JP6.6 | S3.5 70.48,57.62 73.02,60.16 81.91,60.16
  Bottom 0.813: 98.42,43.65 99.69,44.92 JP6.6 | 85.72,38.57 97.15,38.57
PC3  (via drill 0.7 pad 1.93)
  Top 0.406: v89.53,60.16 v94.61,60.16
  Bottom 0.406: 95.88,43.65 IC1.25
  Bottom 0.61: 98.42,55.08 100.96,55.08 103.5,57.62 104.77,57.62 104.21,58.18 | 98.42,55.08 97.15,53.81 JP6.5 | S3.7 67.94,62.7 67.94,65.24 69.21,66.51 80.64,66.51 81.91,65.24 81.91,63.97 85.72,60.16 v89.53,60.16 | v94.61,60.16 95.88,60.16 97.15,58.89 97.15,56.35 98.42,55.08 | 104.21,58.18 104.13,58.26 | 104.21,58.18 S2.3
  Bottom 0.813: 95.88,43.65 97.15,44.92 JP6.5
PC4  (via drill 0.7 pad 1.93)
  Top 0.406: v89.53,56.35 v94.61,56.35
  Bottom 0.406: v94.61,56.35 R7.2
  Bottom 0.61: v89.53,56.35 86.99,56.35 86.99,56.98 78.73,65.24 73.02,65.24 67.94,60.16 S3.6
  Bottom 0.813: IC1.26 93.34,43.65 94.61,44.92 JP6.4 R7.2
PC5
  Bottom 0.61: 92.07,61.43 91.44,62.06 85.72,62.06 84.45,63.34 84.45,64.61 81.27,67.78 76.83,67.78 75.56,69.05 65.4,69.05 64.13,67.78 S3.8
  Bottom 0.813: IC1.27 90.8,43.65 92.07,44.92 JP6.3 R6.2 92.07,61.43
PC6
  Bottom 0.813: IC1.28 88.26,43.65 89.53,44.92 JP6.2 R5.2
PC7
  Bottom 0.813: IC1.29 86.99,44.92 JP6.1 R4.2
PD0  (via drill 0.7 pad 1.93)
  Top 0.406: v109.85,38.57 v114.93,43.65 | v103.5,32.22 v109.85,32.22
  Bottom 0.61: S7.4 116.2,47.46 114.93,46.19 v114.93,43.65 | IC1.14 90.8,25.87 93.34,23.33 JP8.8
  Bottom 0.813: IC4.8 JP8.8 | v109.85,32.22 v109.85,38.57 | v103.5,32.22 93.34,32.22 90.8,29.68 IC1.14
PD1  (via drill 0.7 pad 1.93)
  Top 0.406: v108.58,41.11 v112.39,46.19
  Bottom 0.61: S7.3 116.2,50 v112.39,46.19 | IC1.15 93.34,26.5 95.88,23.96 JP8.7
  Bottom 0.813: IC4.7 JP8.7 | IC1.15 93.34,28.41 94.61,29.68 104.77,29.68 106.04,30.95 106.04,38.57 v108.58,41.11
PD2
  Bottom 0.61: IC1.16 95.88,26.5 98.42,23.96 JP8.6
  Bottom 0.813: IC4.6 JP8.6
PD3
  Bottom 0.61: IC1.17 98.42,26.5 100.96,23.96 JP8.5
  Bottom 0.813: IC4.5 JP8.5
PD4
  Bottom 0.61: IC1.18 100.96,25.87 103.5,23.33 JP8.4
  Bottom 0.813: IC4.4 JP8.4
PD5
  Bottom 0.61: IC1.19 103.5,25.87 106.04,23.33 JP8.3
  Bottom 0.813: IC4.3 JP8.3
PD6
  Bottom 0.61: IC1.20 108.58,24.6 JP8.2
  Bottom 0.813: IC4.2 JP8.2
PD7
  Bottom 0.61: IC4.1 JP8.1 111.12,22.06 112.39,23.33 112.39,39.84 108.58,43.65 107.31,43.65 IC1.21
RESET  (via drill 0.6 pad 1.93, 0.7 pad 1.93)
  Top 0.305: v51.43,30.95 v45.08,30.95 | v73.02,30.95 v60.32,30.95
  Top 0.406: v41.27,74.13 v41.27,66.51
  Top 0.61: v38.73,65.24 v38.73,55.08
  Bottom 0.406: 35.48,48.17 35.55,48.09 | 35.48,48.17 S1.2 | 34.92,48.73 35.48,48.17 | v41.27,66.51 41.27,65.24
  Bottom 0.61: v38.73,55.08 38.73,51.27 36.19,51.27 34.92,50 34.92,48.73 36.19,47.46 36.19,46.19 37.46,45.56 43.18,45.56 45.08,43.65 45.08,41.11 46.35,39.84 75.56,39.84 75.56,33.49 78.1,30.95 | JTAG.6 43.81,62.7 41.27,65.24 v38.73,65.24 | 78.1,30.95 IC1.9 | ISP.5 43.81,29.68 v45.08,30.95 | v60.32,30.95 v51.43,30.95 | 78.1,30.95 v73.02,30.95 | R2.1 17.14,53.81 15.87,55.08 5.71,55.08 1.9,57.62 1.9,67.78 9.52,75.4 29.84,75.4 31.11,74.13 v41.27,74.13

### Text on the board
Bottom: ZAZA M32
